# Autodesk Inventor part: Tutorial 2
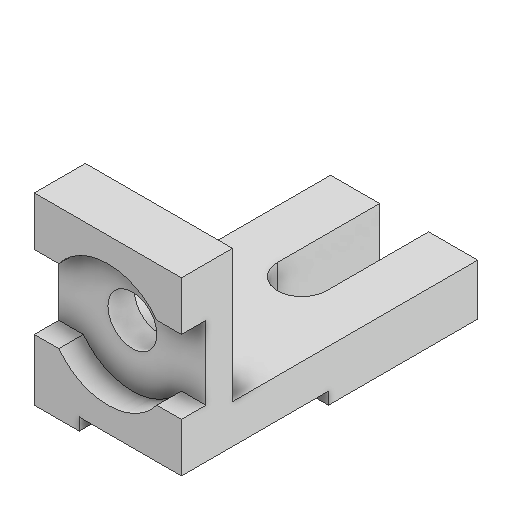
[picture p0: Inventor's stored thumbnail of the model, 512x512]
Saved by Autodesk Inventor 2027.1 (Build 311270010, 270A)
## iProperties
Created: 2021-03
Part Number: Tutorial 2
Material: Generic
Document SubType Name: Modeling
Designer: ASUS Laptop
Density: 1 g/cm^3
Appearance: Default
Author: ASUS Laptop
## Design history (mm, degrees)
sketch "Sketch1"
  geometry: L1 (0, 0)-(90, 0); L2 (90, 0)-(90, -25); L3 (90, -25)-(25, -25); L4 (25, -25)-(25, -145); L5 (25, -145)-(0, -145); L6 (0, -145)-(0, 0)
  constraints: 12 end point, 6 perpendicular, 1 horizontal
  dimensions: "d0" = 145 distance of L5.end L1.start; "d1" = 90 distance between parallel lines of L2 L6; "d2" = 25 distance of L1.end L2.end
extrude "Extrusion1" new body sketch "Sketch1" stored distance "d4" = 72; taper "d5" = 0 deg
sketch "Sketch2"
  geometry: L1 (0, 0)-(72, 0); L2 (72, 0)-(72, 6); L3 (72, 6)-(0, 6); L4 (0, 6)-(0, 0)
  constraints: 8 end point, 2 parallel, 1 horizontal, 1 perpendicular
  dimensions: "d6" = 72 distance of L1.start L1.end; "d7" = 6 distance between parallel lines of L1 L3
extrude "Extrusion2" cut sketch "Sketch2" distance "d8" = 50; taper "d9" = 0 deg
sketch "Sketch3"
  geometry: L1 (12, -24)-(0, -24); L2 (0, -90)-(0, 0) reference; L3 (0, -24)-(0, -60); L4 (0, -60)-(12, -60); L5 (60, -24)-(72, -24); L6 (72, 0)-(72, -84) reference; L7 (72, -24)-(72, -60); L8 (72, -60)-(60, -60); L9 (72, -90)-(22, -90) reference; L10 (0, -90)-(22, -90) reference; A1 r 30 centre (36, -42) between (12, -60) and (60, -60); A2 r 30 centre (36, -42) between (60, -24) and (12, -24); 3 further points
  constraints: 12 end point, 4 point on circle, 4 point on line, 2 centre point, 2 perpendicular, 1 collinear, 1 concentric, 1 horizontal, 1 parallel, 1 vertical
  dimensions: "d10" = 30 radius of A2; "d11" = 36 distance from line of A1.centre L2; "d12" = 48 distance from line of L9 A1.centre; "d13" = 30 distance between parallel lines of L4 L10; "d14" = 36 distance between parallel lines of L4 L1
extrude "Extrusion3" cut sketch "Sketch3" distance "d15" = 12; taper "d16" = 0 deg
sketch "Sketch4"
  geometry: C1 r 12 at (36, -42); A1 r 30 centre (36, -42) between (60, -24) and (12, -24) reference; 1 further point
  constraints: 1 centre point, 1 concentric
  dimensions: "d17" = 24 diameter of C1
extrude "Extrusion4" cut sketch "Sketch4" extent not by distance; stored distance "d18" = 10; taper "d19" = 0 deg
sketch "Sketch5"
  geometry: L1 (24, 120)-(24, 70); L2 (48, 70)-(48, 120); L3 (48, 120)-(24, 120); L4 (72, 120)-(72, 0) reference; A1 r 12 centre (36, 70) between (24, 70) and (48, 70); 2 further points
  constraints: 6 end point, 2 point on circle, 2 tangent, 1 centre point, 1 parallel, 1 perpendicular, 1 point on line, 1 vertical
  dimensions: "d20" = 36 distance from line of A1.centre L4; "d21" = 12 radius of A1; "d22" = 50 distance of L2.start L2.end
extrude "Extrusion5" cut sketch "Sketch5" extent not by distance; stored distance "d23" = 0; taper "d24" = 0 deg
body "Solid1"
